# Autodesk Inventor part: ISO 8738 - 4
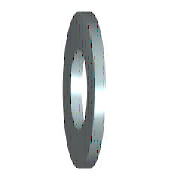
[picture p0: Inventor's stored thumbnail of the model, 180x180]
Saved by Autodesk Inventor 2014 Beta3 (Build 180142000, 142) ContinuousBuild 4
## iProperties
Created: 2010-11
Part Number: ISO 8738 - 4
Material: Steel
Description: Washer
Document SubType Name: Modeling
Standard: ISO 8738
Designer: Beta-8540w
Standard Revision: 1992
Standards Organization: DIN
Language: en-US
Size Designation: 4
Categories: <MemberInstance><Categories><Category DisplayName="Fasteners" InternalName="e4da775c-781d-43d5-af7c-5136215cf5a6" Mnemonic="FSTN"><Category DisplayName="Washers
Density: 7.85 g/cm^3
Appearance: Steel
IsCustomPart: 0
Author: Beta-8540w
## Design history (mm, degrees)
sketch "Sketch"
  geometry: C1 r 4 at (0, 0); C2 r 2 at (0, 0); 1 further point
  constraints: 2 centre point, 2 coincident
  dimensions: "d0" = 4 diameter of C2 (= SD1); "d1" = 8 diameter of C1 (= SD2)
extrude "Body" new body sketch "Sketch" distance "d2" = 0.8 (= SD); taper "d3" = 0 deg
workaxis "Work Axis1"
workplane "Work Plane1"
body "Solid1"
other parameters: "SD1" = 4 [user parameter; used in 1 equation term], "SD2" = 8 [user parameter; used in 1 equation term], "SD" = 0.8 [user parameter; used in 1 equation term], "d4" = 0, "d5" = 0, "d6" = 0, "d7" = 0, "NND" = 4 [user parameter]
